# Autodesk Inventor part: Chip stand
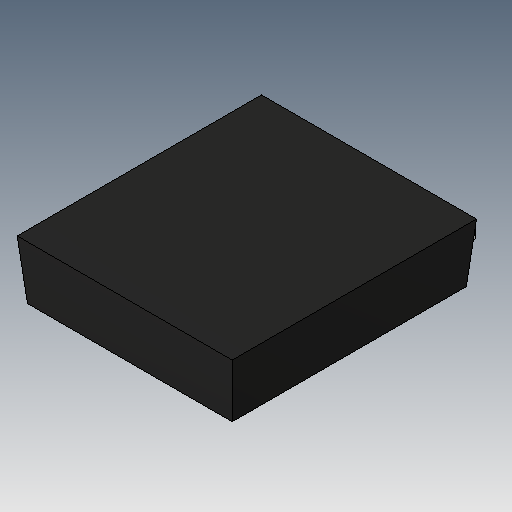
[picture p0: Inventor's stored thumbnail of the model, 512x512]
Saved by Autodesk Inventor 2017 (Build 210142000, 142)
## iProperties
Created: 2005-12
Part Number: Chip stand
Material: Generic
Document SubType Name: Modeling
Designer: DanielSeverino
Density: 1 g/cm^3
Appearance: Default
Author: DanielSeverino
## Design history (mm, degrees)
feature "Solid1"
body "Solid2"
